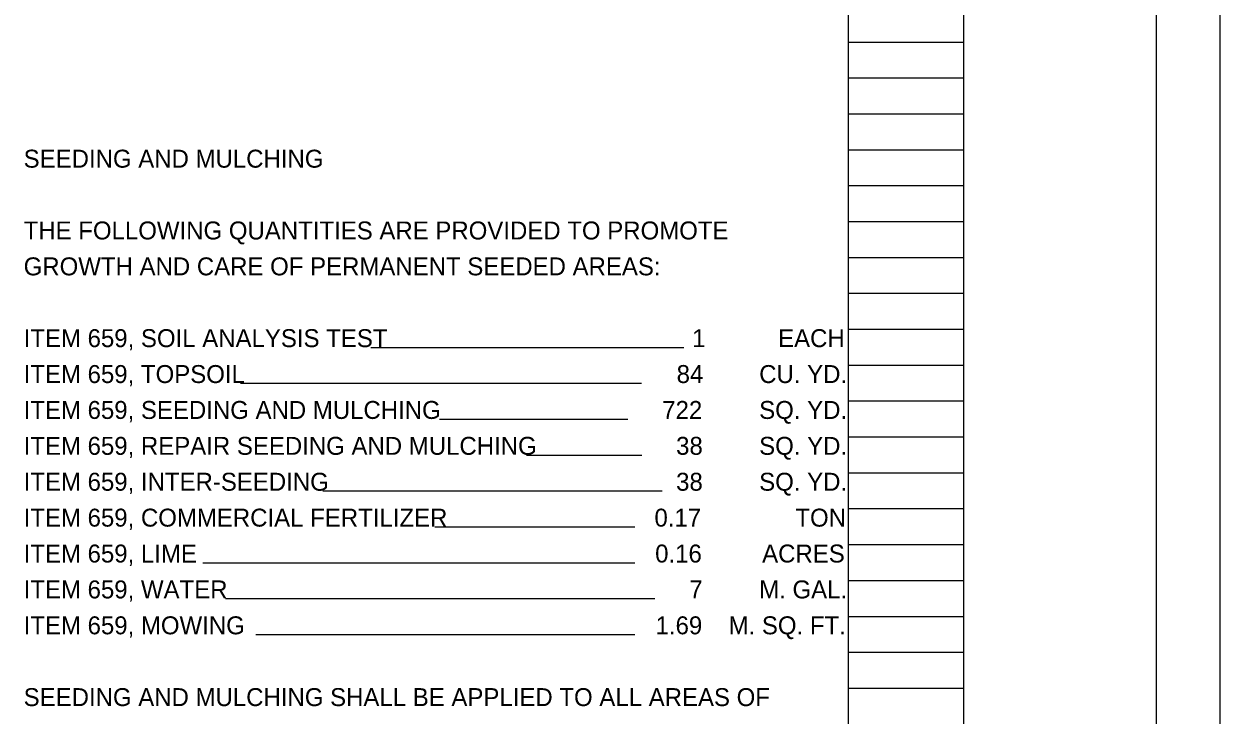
# Model space of a CAD drawing. Extents: x 0 to 34, y 0 to 22.
# Drawn here: x 24.66 to 34, y 5.53 to 10.92 of the extents above; entities that cross this region are included whole.
import ezdxf

# ---------------------------------------------------------------- set-up
doc = ezdxf.new("R2010")
doc.units = 0
for name, color, linetype in [('SH_Border', 7, 'Continuous'), ('SH_Cut_Line', 7, 'Continuous'), ('SH_Data', 7, 'Continuous'), ('SH_Text', 7, 'Continuous')]:
    doc.layers.add(name, color=color, linetype=linetype)

msp = doc.modelspace()

# ---------------------------------------------------------------- linework, layer by layer
at = {"layer": 'SH_Border'}
msp.add_line((32, 0.5), (32, 21.5), dxfattribs=at)
msp.add_lwpolyline([(1.5, 21.5), (33.5, 21.5), (33.5, 0.5), (1.5, 0.5)], close=True, dxfattribs=at)
at = {"layer": 'SH_Cut_Line'}
msp.add_lwpolyline([(0, 0), (34, 0), (34, 22), (0, 22)], close=True, dxfattribs=at)
at = {"layer": 'SH_Data'}
for p, q in [((31.1, 0.98), (31.1, 21.14)), ((32, 0.98), (32, 21.14)), ((31.1, 10.78), (32, 10.78)), ((31.1, 10.5), (32, 10.5)), ((31.1, 10.22), (32, 10.22)), ((31.1, 9.94), (32, 9.94)), ((31.1, 9.66), (32, 9.66)), ((31.1, 9.38), (32, 9.38)), ((31.1, 9.1), (32, 9.1)), ((31.1, 8.82), (32, 8.82)), ((31.1, 8.54), (32, 8.54)), ((29.8127, 8.3956), (27.3692, 8.3956)), ((31.1, 8.26), (32, 8.26)), ((29.4843, 8.1156), (26.3521, 8.1156)), ((31.1, 7.98), (32, 7.98)), ((29.3766, 7.8356), (27.9065, 7.8356)), ((31.1, 7.7), (32, 7.7)), ((29.4853, 7.5556), (28.5867, 7.5556)), ((31.1, 7.42), (32, 7.42)), ((29.6453, 7.2756), (26.9961, 7.2756)), ((31.1, 7.14), (32, 7.14)), ((29.43, 6.9956), (27.8708, 6.9956)), ((31.1, 6.86), (32, 6.86)), ((29.431, 6.7156), (26.058, 6.7156)), ((31.1, 6.58), (32, 6.58)), ((29.5876, 6.4356), (26.235, 6.4356)), ((31.1, 6.3), (32, 6.3)), ((29.4306, 6.1556), (26.472, 6.1556)), ((31.1, 6.02), (32, 6.02)), ((31.1, 5.74), (32, 5.74))]:
    msp.add_line(p, q, dxfattribs=at)

# ---------------------------------------------------------------- texts
at = {"layer": 'SH_Text'}
for s, p in [('SEEDING AND MULCHING', (24.66, 9.8)), ('THE FOLLOWING QUANTITIES ARE PROVIDED TO PROMOTE', (24.66, 9.24)), ('GROWTH AND CARE OF PERMANENT SEEDED AREAS:', (24.66, 8.96)), ('ITEM 659, SOIL ANALYSIS TEST', (24.66, 8.4)), ('1', (29.879, 8.4)), ('EACH', (30.5497, 8.4)), ('ITEM 659, TOPSOIL', (24.66, 8.12)), ('84', (29.7576, 8.12)), ('CU. YD.', (30.4021, 8.12)), ('ITEM 659, SEEDING AND MULCHING', (24.66, 7.84)), ('722', (29.6453, 7.84)), ('SQ. YD.', (30.402, 7.84)), ('ITEM 659, REPAIR SEEDING AND MULCHING', (24.66, 7.56)), ('38', (29.7536, 7.56)), ('SQ. YD.', (30.402, 7.56)), ('ITEM 659, INTER-SEEDING', (24.66, 7.28)), ('38', (29.7536, 7.28)), ('SQ. YD.', (30.402, 7.28)), ('ITEM 659, COMMERCIAL FERTILIZER', (24.66, 7)), ('0.17', (29.5845, 7)), ('TON', (30.6845, 7)), ('ITEM 659, LIME', (24.66, 6.72)), ('0.16', (29.59, 6.72)), ('ACRES', (30.4251, 6.72)), ('ITEM 659, WATER', (24.66, 6.44)), ('7', (29.8563, 6.44)), ('M. GAL.', (30.4021, 6.44)), ('ITEM 659, MOWING', (24.66, 6.16)), ('1.69', (29.5932, 6.16)), ('M. SQ. FT.', (30.1632, 6.16)), ('SEEDING AND MULCHING SHALL BE APPLIED TO ALL AREAS OF', (24.66, 5.6))]:
    msp.add_text(s, height=0.14, dxfattribs=at).set_placement(p)

doc.saveas('drawing.dxf')
